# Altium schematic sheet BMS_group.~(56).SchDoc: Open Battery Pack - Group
size A3; Author: Morgane Vallée; Revision: 1.0; SheetNumber: 2; SheetTotal: 3
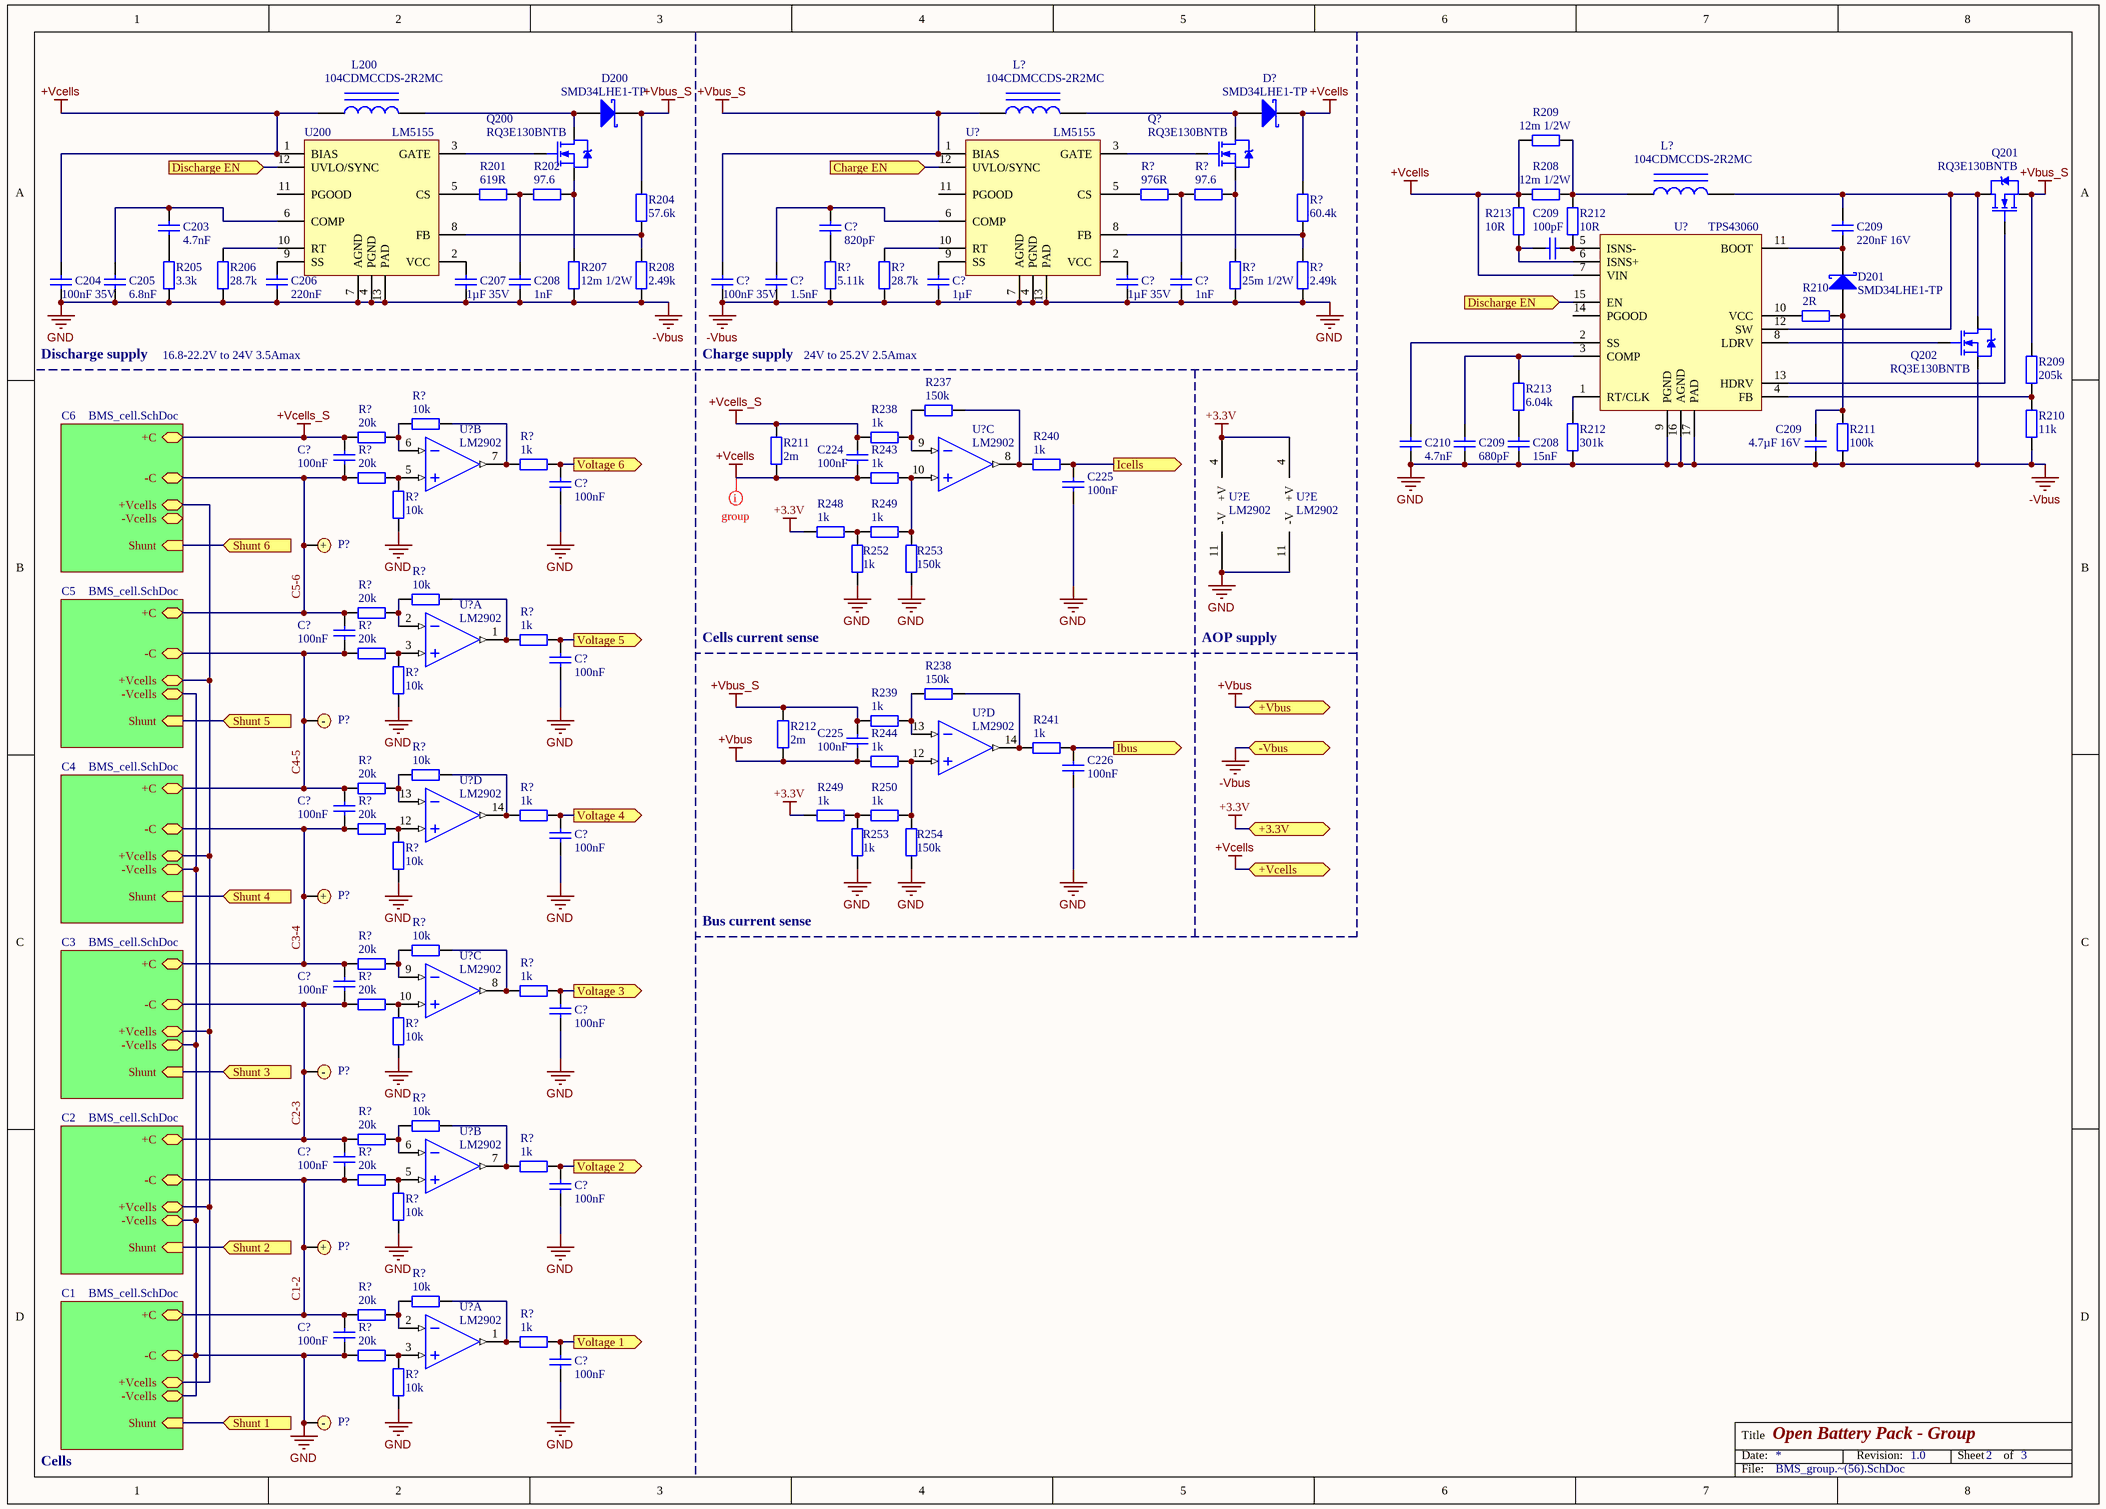
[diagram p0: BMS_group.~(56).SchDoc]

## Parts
(Parts that share a designator on the sheet are numbered #1, #2 ... from top to bottom, then left to right.)
C203  4.7nF  [C0603]
C204  100nF 35V  [C0603]
C205  6.8nF  [C0603]
C206  220nF  [C0603]
C207  1µF 35V  [C0805]
C208#1  1nF  [C0603]
C208#2  15nF  [C0805]
C209#1  220nF 16V  [C0805]
C209#2  100pF  [C0805]
C209#3  680pF  [C0805]
C209#4  4.7µF 16V  [C0805]
C210  4.7nF  [C0805]
C224  100nF  [C0603]
C225#1  100nF  [C0603]
C225#2  100nF  [C0603]
C226  100nF  [C0603]
C?#1  820pF  [C0603]
C?#2  100nF 35V  [C0603]
C?#3  1.5nF  [C0603]
C?#4  1µF  [C0603]
C?#5  1µF 35V  [C0805]
C?#6  1nF  [C0603]
C?#7  100nF  [C0603]
C?#8  100nF  [C0603]
C?#9  100nF  [C0603]
C?#10  100nF  [C0603]
C?#11  100nF  [C0603]
C?#12  100nF  [C0603]
C?#13  100nF  [C0603]
C?#14  100nF  [C0603]
C?#15  100nF  [C0603]
C?#16  100nF  [C0603]
C?#17  100nF  [C0603]
C?#18  100nF  [C0603]
D200  SMD34LHE1-TP  [SOD-123H]
D201  SMD34LHE1-TP  [SOD-123H]
D?  SMD34LHE1-TP  [SOD-123H]
L200  104CDMCCDS-2R2MC  [SELF_SMD_8x8]
L?#1  104CDMCCDS-2R2MC  [SELF_SMD_8x8]
L?#2  104CDMCCDS-2R2MC  [SELF_SMD_8x8]
P?#1  Bat+  [Keystone 241]  (value not drawn)
P?#2  Bat-  [Keystone 2993]  (value not drawn)
P?#3  Bat+  [Keystone 241]  (value not drawn)
P?#4  Bat-  [Keystone 2993]  (value not drawn)
P?#5  Bat+  [Keystone 241]  (value not drawn)
P?#6  Bat-  [Keystone 2993]  (value not drawn)
Q200  RQ3E130BNTB  [INFINEON PG-TSDSON-8]
Q201  RQ3E130BNTB  [INFINEON PG-TSDSON-8]
Q202  RQ3E130BNTB  [INFINEON PG-TSDSON-8]
Q?  RQ3E130BNTB  [INFINEON PG-TSDSON-8]
R201  619R  [R0603]
R202  97.6  [R0603]
R204  57.6k  [R0603]
R205  3.3k  [R0603]
R206  28.7k  [R0603]
R207  12m 1/2W  [R1206]
R208#1  12m 1/2W  [R1206]
R208#2  2.49k  [R0603]
R209#1  12m 1/2W  [R1206]
R209#2  205k  [R0603]
R210#1  2R  [R0603]
R210#2  11k  [R0603]
R211#1  100k  [R0603]
R211#2  2m  [R1206]
R212#1  10R  [R0603]
R212#2  301k  [R0603]
R212#3  2m  [R1206]
R213#1  10R  [R0603]
R213#2  6.04k  [R0603]
R237  150k  [R0603]
R238#1  1k  [R0603]
R238#2  150k  [R0603]
R239  1k  [R0603]
R240  1k  [R0603]
R241  1k  [R0603]
R243  1k  [R0603]
R244  1k  [R0603]
R248  1k  [R0603]
R249#1  1k  [R0603]
R249#2  1k  [R0603]
R250  1k  [R0603]
R252  1k  [R0603]
R253#1  150k  [R0603]
R253#2  1k  [R0603]
R254  150k  [R0603]
R?#1  976R  [R0603]
R?#2  97.6  [R0603]
R?#3  60.4k  [R0603]
R?#4  5.11k  [R0603]
R?#5  28.7k  [R0603]
R?#6  25m 1/2W  [R1206]
R?#7  2.49k  [R0603]
R?#8  10k  [R0603]
R?#9  20k  [R0603]
R?#10  1k  [R0603]
R?#11  20k  [R0603]
R?#12  10k  [R0603]
R?#13  10k  [R0603]
R?#14  20k  [R0603]
R?#15  1k  [R0603]
R?#16  20k  [R0603]
R?#17  10k  [R0603]
R?#18  10k  [R0603]
R?#19  20k  [R0603]
R?#20  1k  [R0603]
R?#21  20k  [R0603]
R?#22  10k  [R0603]
R?#23  10k  [R0603]
R?#24  20k  [R0603]
R?#25  1k  [R0603]
R?#26  20k  [R0603]
R?#27  10k  [R0603]
R?#28  10k  [R0603]
R?#29  20k  [R0603]
R?#30  1k  [R0603]
R?#31  20k  [R0603]
R?#32  10k  [R0603]
R?#33  10k  [R0603]
R?#34  20k  [R0603]
R?#35  1k  [R0603]
R?#36  20k  [R0603]
R?#37  10k  [R0603]
U200  LM5155  [TI WSON-12]
U?#1  LM5155  [TI WSON-12]
U?#2  TPS43060  [TI WQFN-16 RGH]
U?#3  LM2902  [Atmel SO-14 14S1]  (part B of 5)
U?#4  LM2902  [Atmel SO-14 14S1]  (part C of 5)
U?#5  LM2902  [Atmel SO-14 14S1]  (part E of 5)
U?#6  LM2902  [Atmel SO-14 14S1]  (part E of 5)
U?#7  LM2902  [Atmel SO-14 14S1]  (part A of 5)
U?#8  LM2902  [Atmel SO-14 14S1]  (part D of 5)
U?#9  LM2902  [Atmel SO-14 14S1]  (part D of 5)
U?#10  LM2902  [Atmel SO-14 14S1]  (part C of 5)
U?#11  LM2902  [Atmel SO-14 14S1]  (part B of 5)
U?#12  LM2902  [Atmel SO-14 14S1]  (part A of 5)

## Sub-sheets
C1 = BMS_cell.SchDoc: -C, +C, +Vcells, -Vcells, Shunt (in)
C2 = BMS_cell.SchDoc: -C, +C, +Vcells, -Vcells, Shunt (in)
C3 = BMS_cell.SchDoc: -C, +C, +Vcells, -Vcells, Shunt (in)
C4 = BMS_cell.SchDoc: -C, +C, +Vcells, -Vcells, Shunt (in)
C5 = BMS_cell.SchDoc: -C, +C, +Vcells, -Vcells, Shunt (in)
C6 = BMS_cell.SchDoc: -C, +C, +Vcells, -Vcells, Shunt (in)

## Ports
+3.3V, +Vbus, +Vcells, -Vbus, Charge EN (in), Discharge EN (in), Ibus (out), Icells (out), Shunt 1 (in), Shunt 2 (in), Shunt 3 (in), Shunt 4 (in), Shunt 5 (in), Shunt 6 (in), Voltage 1 (out), Voltage 2 (out), Voltage 3 (out), Voltage 4 (out), Voltage 5 (out), Voltage 6 (out)

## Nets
+3.3V: R248.2 R249#2.2 U?#5.4(+V) U?#6.4(+V) ; port +3.3V
+Vbus: C225#2.2 R212#3.1 R244.2 ; port +Vbus
+Vbus_S: C225#2.1 C?#2.1 D200.3(K) L?#1.1 Q201.2(S) R204.2 R209#2.2 R212#3.2 R239.1 U?#1.1(BIAS)
+Vcells: C204.1 C224.2 D?.3(K) L200.1 R208#1.2 R209#1.2 R211#2.1 R213#1.2 R243.2 R?#3.2 U200.1(BIAS) U?#2.7(VIN) ; port +Vcells
+Vcells_S: C224.1 C?#7.1 R211#2.2 R238#1.1 R?#9.1 ; sheet C6/+C
-Vbus: C204.2 C205.2 C206.2 C207.2 C208#1.2 C208#2.2 C209#3.2 C209#4.2 C210.2 C225#1.2 C226.2 C?#2.2 C?#3.2 C?#4.2 C?#5.2 C?#6.2 C?#8.2 C?#10.2 C?#12.2 C?#14.2 C?#16.2 C?#17.2 C?#18.2 P?#6.1 Q202.2(S) R205.1 R206.1 R207.1 R208#2.1 R210#2.1 R211#1.1 R212#2.1 R252.2 R253#1.1 R253#2.2 R254.1 R?#4.1 R?#5.1 R?#6.1 R?#7.1 R?#12.2 R?#17.2 R?#22.2 R?#27.2 R?#32.2 R?#36.2 R?#37.2 U200.4(PGND) U200.7(AGND) U200.13(PAD) U?#1.4(PGND) U?#1.7(AGND) U?#1.13(PAD) U?#2.9(PGND) U?#2.16(AGND) U?#2.17(PAD) U?#5.11(-V) U?#6.11(-V) ; port -Vbus, sheet C1/-C, sheet C1/-Vcells, sheet C2/-Vcells, sheet C3/-Vcells, sheet C4/-Vcells, sheet C5/-Vcells  [also labelled GND]
C1-2: C?#15.2 C?#17.1 P?#5.1 R?#31.2 R?#34.1 ; sheet C1/+C, sheet C2/-C
C2-3: C?#13.2 C?#15.1 P?#4.1 R?#26.2 R?#29.1 ; sheet C2/+C, sheet C3/-C
C3-4: C?#11.2 C?#13.1 P?#3.1 R?#21.2 R?#24.1 ; sheet C3/+C, sheet C4/-C
C4-5: C?#9.2 C?#11.1 P?#2.1 R?#16.2 R?#19.1 ; sheet C4/+C, sheet C5/-C
C5-6: C?#7.2 C?#9.1 P?#1.1 R?#11.2 R?#14.1 ; sheet C5/+C, sheet C6/-C
Charge EN: U?#1.12(UVLO/SYNC) ; port Charge EN
Discharge EN: U200.12(UVLO/SYNC) U?#2.15(EN) ; port Discharge EN
Ibus: C226.1 R241.1 ; port Ibus
Icells: C225#1.1 R240.1 ; port Icells
Shunt 1: port Shunt 1, sheet C1/Shunt
Shunt 2: port Shunt 2, sheet C2/Shunt
Shunt 3: port Shunt 3, sheet C3/Shunt
Shunt 4: port Shunt 4, sheet C4/Shunt
Shunt 5: port Shunt 5, sheet C5/Shunt
Shunt 6: port Shunt 6, sheet C6/Shunt
Voltage 1: C?#18.1 R?#35.1 ; port Voltage 1
Voltage 2: C?#16.1 R?#30.1 ; port Voltage 2
Voltage 3: C?#14.1 R?#25.1 ; port Voltage 3
Voltage 4: C?#12.1 R?#20.1 ; port Voltage 4
Voltage 5: C?#10.1 R?#15.1 ; port Voltage 5
Voltage 6: C?#8.1 R?#10.1 ; port Voltage 6
NetC203_1: C203.1 C205.1 U200.6(COMP)
NetC203_2: C203.2 R205.2
NetC206_1: C206.1 U200.9(SS)
NetC207_1: C207.1 U200.2(VCC)
NetC208#1_1: C208#1.1 R201.1 R202.2
NetC208#2_1: C208#2.1 R213#2.1
NetC209#1_1: C209#1.1 L?#2.2 Q201.3(D) Q202.3(D) U?#2.12(SW)
NetC209#1_2: C209#1.2 D201.3(K) U?#2.11(BOOT)
NetC209#2_1: C209#2.1 R213#1.1 U?#2.6(ISNS+)
NetC209#2_2: C209#2.2 R212#1.1 U?#2.5(ISNS-)
NetC209#3_1: C209#3.1 R213#2.2 U?#2.3(COMP)
NetC209#4_1: C209#4.1 D201.1(A) R210#1.1 R211#1.2
NetC210_1: C210.1 U?#2.2(SS)
NetC?#1_1: C?#1.1 C?#3.1 U?#1.6(COMP)
NetC?#1_2: C?#1.2 R?#4.2
NetC?#4_1: C?#4.1 U?#1.9(SS)
NetC?#5_1: C?#5.1 U?#1.2(VCC)
NetC?#6_1: C?#6.1 R?#1.1 R?#2.2
NetD200_1: D200.1(A) L200.2 Q200.3(D)
NetD?_1: D?.1(A) L?#1.2 Q?.3(D)
NetL?#2_1: L?#2.1 R208#1.1 R209#1.1 R212#1.2
NetQ200_1: Q200.1(G) U200.3(GATE)
NetQ200_2: Q200.2(S) R202.1 R207.2
NetQ201_1: Q201.1(G) U?#2.13(HDRV)
NetQ202_1: Q202.1(G) U?#2.8(LDRV)
NetQ?_1: Q?.1(G) U?#1.3(GATE)
NetQ?_2: Q?.2(S) R?#2.1 R?#6.2
NetR201_2: R201.2 U200.5(CS)
NetR204_1: R204.1 R208#2.2 U200.8(FB)
NetR206_2: R206.2 U200.10(RT)
NetR209#2_1: R209#2.1 R210#2.2 U?#2.4(FB)
NetR210#1_2: R210#1.2 U?#2.10(VCC)
NetR212#2_2: R212#2.2 U?#2.1(RT/CLK)
NetR237_1: R237.1 R240.2 U?#4.8(OUT)
NetR237_2: R237.2 R238#1.2 U?#4.9(IN-)
NetR238#2_1: R238#2.1 R241.2 U?#8.14(OUT)
NetR238#2_2: R238#2.2 R239.2 U?#8.13(IN-)
NetR243_1: R243.1 R249#1.1 R253#1.2 U?#4.10(IN+)
NetR244_1: R244.1 R250.1 R254.2 U?#8.12(IN+)
NetR248_1: R248.1 R249#1.2 R252.1
NetR249#2_1: R249#2.1 R250.2 R253#2.1
NetR?#1_2: R?#1.2 U?#1.5(CS)
NetR?#3_1: R?#3.1 R?#7.2 U?#1.8(FB)
NetR?#5_2: R?#5.2 U?#1.10(RT)
NetR?#8_1: R?#8.1 R?#9.2 U?#3.6(IN-)
NetR?#8_2: R?#8.2 R?#10.2 U?#3.7(OUT)
NetR?#11_1: R?#11.1 R?#12.1 U?#3.5(IN+)
NetR?#13_1: R?#13.1 R?#14.2 U?#7.2(IN-)
NetR?#13_2: R?#13.2 R?#15.2 U?#7.1(OUT)
NetR?#16_1: R?#16.1 R?#17.1 U?#7.3(IN+)
NetR?#18_1: R?#18.1 R?#19.2 U?#9.13(IN-)
NetR?#18_2: R?#18.2 R?#20.2 U?#9.14(OUT)
NetR?#21_1: R?#21.1 R?#22.1 U?#9.12(IN+)
NetR?#23_1: R?#23.1 R?#24.2 U?#10.9(IN-)
NetR?#23_2: R?#23.2 R?#25.2 U?#10.8(OUT)
NetR?#26_1: R?#26.1 R?#27.1 U?#10.10(IN+)
NetR?#28_1: R?#28.1 R?#29.2 U?#11.6(IN-)
NetR?#28_2: R?#28.2 R?#30.2 U?#11.7(OUT)
NetR?#31_1: R?#31.1 R?#32.1 U?#11.5(IN+)
NetR?#33_1: R?#33.1 R?#34.2 U?#12.2(IN-)
NetR?#33_2: R?#33.2 R?#35.2 U?#12.1(OUT)
NetR?#36_1: R?#36.1 R?#37.1 U?#12.3(IN+)
(unnamed): sheet C1/+Vcells, sheet C2/+Vcells, sheet C3/+Vcells, sheet C4/+Vcells, sheet C5/+Vcells, sheet C6/+Vcells

Not connected (* = marked no-connect by the designer): U200 11(PGOOD); U?#1 11(PGOOD); U?#2 14(PGOOD)

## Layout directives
net class Group: +Vcells

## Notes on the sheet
- Discharge supply
- 16.8-22.2V to 24V 3.5Amax
- Charge supply
- 24V to 25.2V 2.5Amax
- Cells current sense
- AOP supply
- Bus current sense
- Cells

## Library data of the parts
C203-C207 C208#1 C208#2 C209#1-C209#4 C210 C224 C225#1 C225#2 C226 C?#1-C?#18 = Cap: Capacitor
D200 D201 D? = Diode BAT17
L200 L?#1 L?#2 = Inductor Iron: Magnetic-Core Inductor
P?#1 P?#3 P?#5 = Bat+: Battery contact +
P?#2 P?#4 P?#6 = Bat-: Battery contact -
Q200-Q202 Q? = MOSFET_N
R201 R202 R204-R207 R208#1 R208#2 R209#1 R209#2 R210#1 R210#2 R211#1 R211#2 R212#1-R212#3 R213#1 R213#2 R237 R238#1 R238#2 R239-R241 R243 R244 R248 R249#1 R249#2 R250 R252 R253#1 R253#2 R254 R?#1-R?#37 = Res2: Resistor
U200 U?#1 = LM5155: 2.2-MHz Wide Input Nonsynchronous Boost, SEPIC, Flyback Controller
U?#2 = TPS43060: Low Quiescent Current Synchronous Boost  DC-DC Controller With Wide VIN Range
U?#3-U?#12 = LM2902: Low-power quad operational amplifiers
